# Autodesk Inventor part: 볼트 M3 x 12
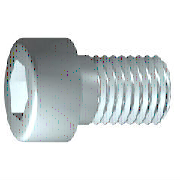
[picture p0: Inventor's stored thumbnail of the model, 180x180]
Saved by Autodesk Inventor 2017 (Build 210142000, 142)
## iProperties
IsCustomPart: 0
Created: 2012-02
Part Number: 볼트 M3 x 12
Material: 강철, 연강
Description: 6각머리 태핑 나사
Document SubType Name: Modeling
Standard: KS B 1003
Designer: mduedu
Standards Organization: KS
Language: ko-KR
Size Designation: M 3 x 12
Categories: <MemberInstance><Categories><Category DisplayName="조임쇠" InternalName="e4da775c-781d-43d5-af7c-5136215cf5a6" Mnemonic="FSTN"><Category DisplayName="볼트" InternalN
Density: 7.86 g/cm^3
Mass: 1.20764 g
Surface Area: 2.30125 cm^2
Volume: 0.153644 cm^3
Appearance: 강철
Author: mduedu
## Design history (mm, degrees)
sketch "스케치1"
  geometry: L1 (-0.867, 0)-(13, 0); L2 (13, 0)-(13, 1.5); L3 (13, 1.5)-(1.25, 1.5); L4 (1.25, 1.5)-(0.943, 1.5); L5 (0.943, 1.5)-(0, 1.5); L6 (0, 1.5)-(0, 2.75); L7 (0, 2.75)-(-3, 2.75); L8 (-3, 2.75)-(-3, 1.443); L9 (-3, 1.443)-(-1.7, 1.443); L10 (-1.7, 1.443)-(-0.867, 0); L11 (-6.2, 0)-(16.2, 0) reference; L12 (0, -0.55)-(0, 3.3) reference; L13 (1.25, 1.5)-(0, 1.5)
  constraints: 22 end point, 6 parallel, 2 collinear, 2 perpendicular, 1 horizontal, 1 point on line
  dimensions: "d1" = 11.75 distance from line of L3.end L2 (= GEL); "d2" = 0.30683 distance of L4.end L3.end (computed from GAL); "d3" = 3 distance between parallel lines of L8 L6 (= KOH); "d4" = 1.3 distance of L8.end L9.end (= INTI); "d5" = 60 deg angle of L10 L1; "d6" = 3 diameter of L3 L1 (= GD); "d7" = 3 diameter of L5 L1 (= BDM); "d8" = 2.88675 diameter of L9 L1 (= 1.1547 x SW); "d9" = 5.5 diameter of L7 L1 (= KOD); "d26" = 13 distance between parallel lines of L12 L2 (= NLG)
revolve "본체" sketch "스케치1" stored, may be unused: angle "d10" = 90 deg
sketch "스케치2"
  geometry: L1 (0, -3.85)-(0, 3.85) reference; L2 (-3.85, 0)-(3.85, 0) reference; L3 (1.443, 0)-(0.722, -1.25); L4 (0.722, -1.25)-(-0.722, -1.25); L5 (-0.722, -1.25)-(-1.443, 0); L6 (-1.443, 0)-(-0.722, 1.25); L7 (-0.722, 1.25)-(0.722, 1.25); L8 (0.722, 1.25)-(1.443, 0); 2 further points
  constraints: 12 end point, 1 coincident, 1 horizontal alignment, 1 point on line, 12 other
extrude "슬롯" join sketch "스케치2" stored distance "d11" = 10; taper "d12" = 0 deg
workplane "Work Plane1"
fillet "Fillet2" dims "d30" = 0.1 (= R)
body "Solid1"
fillet "모깎기1" dims "d17" = 0.3 (= RR)
feature "스레드" dims "d13" = 11.75 (= GEL), "d14" = 0
chamfer "모따기1" distance "d15" = 0.30673 (= -0.5 x SPD + 0.5 x GD); stored, may be unused: second distance "d16" = 0.30673 (= GUL), angle "d27" = 45 deg
other parameters: "GD" = 3 (= NND) [user parameter; used in 2 equation terms], "NLG" = 13 [user parameter; used in 1 equation term], "GEL" = 11.75 [user parameter; used in 2 equation terms], "KOD" = 5.5 [user parameter; used in 1 equation term], "KOH" = 3 [user parameter; used in 1 equation term], "INTI" = 1.3 [user parameter; used in 1 equation term], "GAL" = 0.30673 (= 0.61345 x PTC) [user parameter; used in 1 equation term], "GUL" = 0.30673 (= 0.61345 x PTC) [user parameter; used in 1 equation term], "BDM" = 3 (= NND) [user parameter; used in 1 equation term], "SW" = 2.5 [user parameter; used in 2 equation terms], "RR" = 0.3 [user parameter; used in 1 equation term], "SPD" = 2.38655 (= NND - 1.2269 x PTC) [user parameter; used in 1 equation term], "d19" = 0, "d28" = 0, "d29" = 0, "R" = 0.1 [user parameter; used in 1 equation term], "PHH" = 0.1 [user parameter], "GD1" = 2.38655 (= THREADDIA - 1.2269 x PTC) [user parameter], "THREADDIA" = 3 [user parameter; used in 1 equation term], "FAWI" = 45 deg [user parameter], "PTC" = 0.5 [user parameter; used in 5 equation terms], "NND" = 3 [user parameter; used in 3 equation terms], "TOA" = 30 deg [user parameter], "E0" = 2.8875 (= 1.155 x SW) [user parameter]
